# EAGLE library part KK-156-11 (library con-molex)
KK 156 HEADER Source: http://www.molex.com/pdm_docs/sd/026604100_sd.pdf
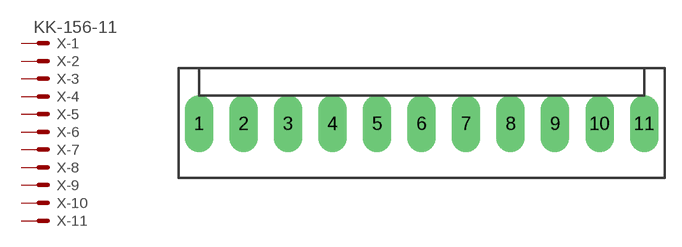
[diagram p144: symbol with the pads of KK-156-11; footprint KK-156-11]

Designator prefix X; gates -1=MV -2=M -3=M -4=M -5=M -6=M -7=M -8=M -9=M -10=M -11=M

## KK-156-11 (OC_FARNELL: unknown; OC_NEWARK: unknown)  [KK-156-11]
1  -1:S  pas
2  -2:S  pas
3  -3:S  pas
4  -4:S  pas
5  -5:S  pas
6  -6:S  pas
7  -7:S  pas
8  -8:S  pas
9  -9:S  pas
10  -10:S  pas
11  -11:S  pas

## Footprint KK-156-11 (pad centres in mm)
KK 156 HEADER Source: http://www.molex.com/pdm_docs/sd/026604100_sd.pdf
drill 1.7 pad 2.184 long: 1 -19.8,0; 2 -15.84,0; 3 -11.88,0; 4 -7.92,0; 5 -3.96,0; 6 0,0; 7 3.96,0; 8 7.92,0; 9 11.88,0; 10 15.84,0; 11 19.8,0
